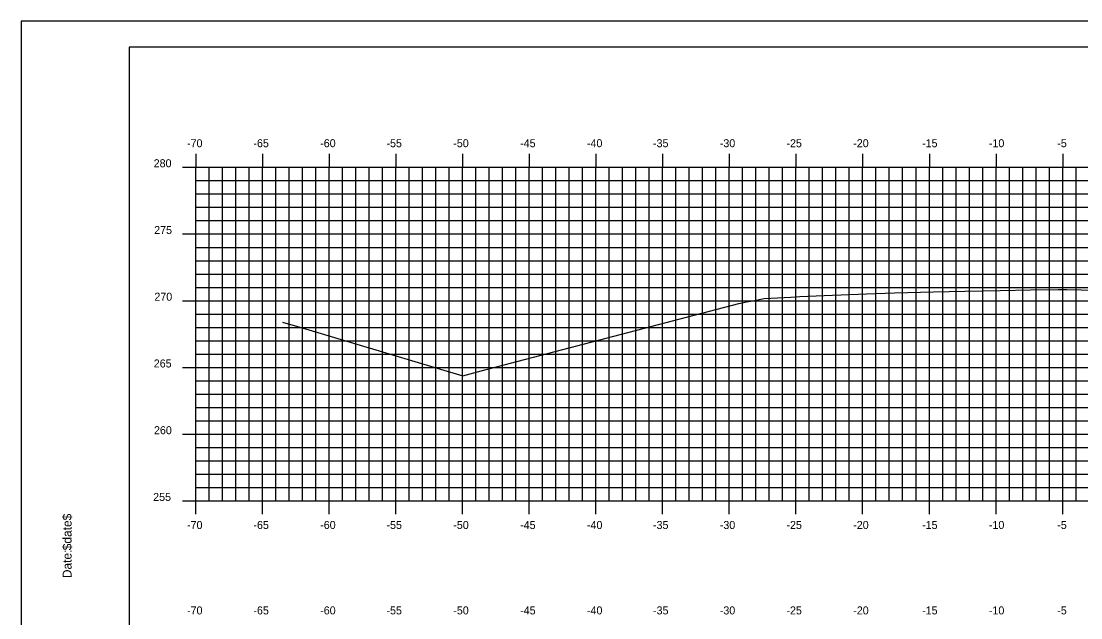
# Model space of a CAD drawing. Extents: x 1168600 to 1177589, y 610178 to 611246.
# Drawn here: x 1176530.8 to 1176610.3, y 610334 to 610378.7 of the extents above; entities that cross this region are included whole.
import ezdxf

# ---------------------------------------------------------------- set-up
doc = ezdxf.new("R2010")
doc.units = 0
for name, color, linetype in [('_Construction', 7, 'Continuous'), ('_Station Equation', 7, 'Continuous'), ('H_V ANNOTATION', 7, 'Continuous'), ('MAJOR', 7, 'Continuous'), ('MINOR', 7, 'Continuous')]:
    doc.layers.add(name, color=color, linetype=linetype)

msp = doc.modelspace()

# ---------------------------------------------------------------- linework, layer by layer
at = {"layer": '_Construction'}
for p, q in [((1176698.898, 610376.801), (1176538.898, 610376.801)), ((1176538.898, 610376.801), (1176538.898, 610271.801))]:
    msp.add_line(p, q, dxfattribs=at)
msp.add_lwpolyline([(1176530.805, 610268.742), (1176700.805, 610268.742), (1176700.805, 610378.742), (1176530.805, 610378.742)], close=True, dxfattribs=at)
at = {"layer": '_Station Equation'}
msp.add_lwpolyline([(1176550.398, 610356.197), (1176551.869, 610355.767), (1176563.916, 610352.178), (1176565.302, 610352.546), (1176584.623, 610357.603), (1176585.198, 610357.717), (1176585.676, 610357.795), (1176586.504, 610357.963), (1176588.524, 610358.079), (1176589.187, 610358.112), (1176591.022, 610358.191), (1176594.194, 610358.328), (1176596.297, 610358.382), (1176599.2, 610358.457), (1176601.571, 610358.508), (1176604.206, 610358.563), (1176606.485, 610358.607), (1176608.566, 610358.646), (1176608.924, 610358.641), (1176609.213, 610358.637), (1176611.353, 610358.595)], dxfattribs=at)
at = {"layer": 'MAJOR'}
for p, q in [((1176543.898, 610368.803), (1176543.898, 610367.801)), ((1176548.898, 610368.803), (1176548.898, 610367.801)), ((1176553.898, 610368.803), (1176553.898, 610367.801)), ((1176558.898, 610368.803), (1176558.898, 610367.801)), ((1176563.898, 610368.803), (1176563.898, 610367.801)), ((1176568.898, 610368.803), (1176568.898, 610367.801)), ((1176573.898, 610368.803), (1176573.898, 610367.801)), ((1176578.898, 610368.803), (1176578.898, 610367.801)), ((1176583.898, 610368.803), (1176583.898, 610367.801)), ((1176588.898, 610368.803), (1176588.898, 610367.801)), ((1176593.898, 610368.803), (1176593.898, 610367.801)), ((1176598.898, 610368.803), (1176598.898, 610367.801)), ((1176603.898, 610368.803), (1176603.898, 610367.801)), ((1176608.898, 610368.803), (1176608.898, 610367.801)), ((1176542.896, 610367.801), (1176543.898, 610367.801)), ((1176543.898, 610367.801), (1176683.898, 610367.801)), ((1176543.898, 610342.801), (1176543.898, 610367.801)), ((1176543.898, 610342.801), (1176543.898, 610367.801)), ((1176543.898, 610367.801), (1176683.898, 610367.801)), ((1176548.898, 610342.801), (1176548.898, 610367.801)), ((1176553.898, 610342.801), (1176553.898, 610367.801)), ((1176558.898, 610342.801), (1176558.898, 610367.801)), ((1176563.898, 610342.801), (1176563.898, 610367.801)), ((1176568.898, 610342.801), (1176568.898, 610367.801)), ((1176573.898, 610342.801), (1176573.898, 610367.801)), ((1176578.898, 610342.801), (1176578.898, 610367.801)), ((1176583.898, 610342.801), (1176583.898, 610367.801)), ((1176588.898, 610342.801), (1176588.898, 610367.801)), ((1176593.898, 610342.801), (1176593.898, 610367.801)), ((1176598.898, 610342.801), (1176598.898, 610367.801)), ((1176603.898, 610342.801), (1176603.898, 610367.801)), ((1176608.898, 610342.801), (1176608.898, 610367.801)), ((1176542.896, 610362.801), (1176543.898, 610362.801)), ((1176543.898, 610362.801), (1176683.898, 610362.801)), ((1176542.896, 610357.801), (1176543.898, 610357.801)), ((1176543.898, 610357.801), (1176683.898, 610357.801)), ((1176542.896, 610352.801), (1176543.898, 610352.801)), ((1176543.898, 610352.801), (1176683.898, 610352.801)), ((1176542.896, 610347.801), (1176543.898, 610347.801)), ((1176543.898, 610347.801), (1176683.898, 610347.801)), ((1176542.896, 610342.801), (1176543.898, 610342.801)), ((1176543.898, 610342.801), (1176683.898, 610342.801)), ((1176543.898, 610342.801), (1176683.898, 610342.801)), ((1176543.898, 610341.799), (1176543.898, 610342.801)), ((1176548.898, 610341.799), (1176548.898, 610342.801)), ((1176553.898, 610341.799), (1176553.898, 610342.801)), ((1176558.898, 610341.799), (1176558.898, 610342.801)), ((1176563.898, 610341.799), (1176563.898, 610342.801)), ((1176568.898, 610341.799), (1176568.898, 610342.801)), ((1176573.898, 610341.799), (1176573.898, 610342.801)), ((1176578.898, 610341.799), (1176578.898, 610342.801)), ((1176583.898, 610341.799), (1176583.898, 610342.801)), ((1176588.898, 610341.799), (1176588.898, 610342.801)), ((1176593.898, 610341.799), (1176593.898, 610342.801)), ((1176598.898, 610341.799), (1176598.898, 610342.801)), ((1176603.898, 610341.799), (1176603.898, 610342.801)), ((1176608.898, 610341.799), (1176608.898, 610342.801))]:
    msp.add_line(p, q, dxfattribs=at)
at = {"layer": 'MINOR'}
for p, q in [((1176544.898, 610342.801), (1176544.898, 610367.801)), ((1176545.898, 610342.801), (1176545.898, 610367.801)), ((1176546.898, 610342.801), (1176546.898, 610367.801)), ((1176547.898, 610342.801), (1176547.898, 610367.801)), ((1176549.898, 610342.801), (1176549.898, 610367.801)), ((1176550.898, 610342.801), (1176550.898, 610367.801)), ((1176551.898, 610342.801), (1176551.898, 610367.801)), ((1176552.898, 610342.801), (1176552.898, 610367.801)), ((1176554.898, 610342.801), (1176554.898, 610367.801)), ((1176555.898, 610342.801), (1176555.898, 610367.801)), ((1176556.898, 610342.801), (1176556.898, 610367.801)), ((1176557.898, 610342.801), (1176557.898, 610367.801)), ((1176559.898, 610342.801), (1176559.898, 610367.801)), ((1176560.898, 610342.801), (1176560.898, 610367.801)), ((1176561.898, 610342.801), (1176561.898, 610367.801)), ((1176562.898, 610342.801), (1176562.898, 610367.801)), ((1176564.898, 610342.801), (1176564.898, 610367.801)), ((1176565.898, 610342.801), (1176565.898, 610367.801)), ((1176566.898, 610342.801), (1176566.898, 610367.801)), ((1176567.898, 610342.801), (1176567.898, 610367.801)), ((1176569.898, 610342.801), (1176569.898, 610367.801)), ((1176570.898, 610342.801), (1176570.898, 610367.801)), ((1176571.898, 610342.801), (1176571.898, 610367.801)), ((1176572.898, 610342.801), (1176572.898, 610367.801)), ((1176574.898, 610342.801), (1176574.898, 610367.801)), ((1176575.898, 610342.801), (1176575.898, 610367.801)), ((1176576.898, 610342.801), (1176576.898, 610367.801)), ((1176577.898, 610342.801), (1176577.898, 610367.801)), ((1176579.898, 610342.801), (1176579.898, 610367.801)), ((1176580.898, 610342.801), (1176580.898, 610367.801)), ((1176581.898, 610342.801), (1176581.898, 610367.801)), ((1176582.898, 610342.801), (1176582.898, 610367.801)), ((1176584.898, 610342.801), (1176584.898, 610367.801)), ((1176585.898, 610342.801), (1176585.898, 610367.801)), ((1176586.898, 610342.801), (1176586.898, 610367.801)), ((1176587.898, 610342.801), (1176587.898, 610367.801)), ((1176589.898, 610342.801), (1176589.898, 610367.801)), ((1176590.898, 610342.801), (1176590.898, 610367.801)), ((1176591.898, 610342.801), (1176591.898, 610367.801)), ((1176592.898, 610342.801), (1176592.898, 610367.801)), ((1176594.898, 610342.801), (1176594.898, 610367.801)), ((1176595.898, 610342.801), (1176595.898, 610367.801)), ((1176596.898, 610342.801), (1176596.898, 610367.801)), ((1176597.898, 610342.801), (1176597.898, 610367.801)), ((1176599.898, 610342.801), (1176599.898, 610367.801)), ((1176600.898, 610342.801), (1176600.898, 610367.801)), ((1176601.898, 610342.801), (1176601.898, 610367.801)), ((1176602.898, 610342.801), (1176602.898, 610367.801)), ((1176604.898, 610342.801), (1176604.898, 610367.801)), ((1176605.898, 610342.801), (1176605.898, 610367.801)), ((1176606.898, 610342.801), (1176606.898, 610367.801)), ((1176607.898, 610342.801), (1176607.898, 610367.801)), ((1176609.898, 610342.801), (1176609.898, 610367.801)), ((1176543.898, 610366.801), (1176683.898, 610366.801)), ((1176543.898, 610366.801), (1176544.9, 610366.801)), ((1176543.898, 610365.801), (1176683.898, 610365.801)), ((1176543.898, 610365.801), (1176544.9, 610365.801)), ((1176543.898, 610364.801), (1176683.898, 610364.801)), ((1176543.898, 610364.801), (1176544.9, 610364.801)), ((1176543.898, 610363.801), (1176683.898, 610363.801)), ((1176543.898, 610363.801), (1176544.9, 610363.801)), ((1176543.898, 610361.801), (1176683.898, 610361.801)), ((1176543.898, 610361.801), (1176544.9, 610361.801)), ((1176543.898, 610360.801), (1176683.898, 610360.801)), ((1176543.898, 610360.801), (1176544.9, 610360.801)), ((1176543.898, 610359.801), (1176683.898, 610359.801)), ((1176543.898, 610359.801), (1176544.9, 610359.801)), ((1176543.898, 610358.801), (1176683.898, 610358.801)), ((1176543.898, 610358.801), (1176544.9, 610358.801)), ((1176543.898, 610356.801), (1176683.898, 610356.801)), ((1176543.898, 610356.801), (1176544.9, 610356.801)), ((1176543.898, 610355.801), (1176683.898, 610355.801)), ((1176543.898, 610355.801), (1176544.9, 610355.801)), ((1176543.898, 610354.801), (1176683.898, 610354.801)), ((1176543.898, 610354.801), (1176544.9, 610354.801)), ((1176543.898, 610353.801), (1176683.898, 610353.801)), ((1176543.898, 610353.801), (1176544.9, 610353.801)), ((1176543.898, 610351.801), (1176683.898, 610351.801)), ((1176543.898, 610351.801), (1176544.9, 610351.801)), ((1176543.898, 610350.801), (1176683.898, 610350.801)), ((1176543.898, 610350.801), (1176544.9, 610350.801)), ((1176543.898, 610349.801), (1176683.898, 610349.801)), ((1176543.898, 610349.801), (1176544.9, 610349.801)), ((1176543.898, 610348.801), (1176683.898, 610348.801)), ((1176543.898, 610348.801), (1176544.9, 610348.801)), ((1176543.898, 610346.801), (1176683.898, 610346.801)), ((1176543.898, 610346.801), (1176544.9, 610346.801)), ((1176543.898, 610345.801), (1176683.898, 610345.801)), ((1176543.898, 610345.801), (1176544.9, 610345.801)), ((1176543.898, 610344.801), (1176683.898, 610344.801)), ((1176543.898, 610344.801), (1176544.9, 610344.801)), ((1176543.898, 610343.801), (1176683.898, 610343.801)), ((1176543.898, 610343.801), (1176544.9, 610343.801))]:
    msp.add_line(p, q, dxfattribs=at)

# ---------------------------------------------------------------- texts
at = {"layer": '_Construction'}
for s, p in [('$date$', (1176534.583, 610339.106)), ('Date:', (1176534.583, 610337.018))]:
    msp.add_text(s, height=0.6696, rotation=90, dxfattribs=at).set_placement(p)
at = {"layer": 'H_V ANNOTATION'}
for s, p in [('-70', (1176543.24, 610369.301)), ('-65', (1176548.216, 610369.301)), ('-60', (1176553.224, 610369.301)), ('-55', (1176558.194, 610369.301)), ('-50', (1176563.202, 610369.301)), ('-45', (1176568.216, 610369.301)), ('-40', (1176573.224, 610369.301)), ('-35', (1176578.178, 610369.301)), ('-30', (1176583.186, 610369.301)), ('-25', (1176588.183, 610369.301)), ('-20', (1176593.191, 610369.301)), ('-15', (1176598.355, 610369.301)), ('-10', (1176603.363, 610369.301)), ('-5', (1176608.489, 610369.301)), ('280', (1176540.739, 610367.801)), ('275', (1176540.776, 610362.801)), ('270', (1176540.792, 610357.801)), ('265', (1176540.744, 610352.801)), ('260', (1176540.76, 610347.801)), ('255', (1176540.701, 610342.801)), ('-70', (1176543.24, 610340.701)), ('-65', (1176548.216, 610340.701)), ('-60', (1176553.224, 610340.701)), ('-55', (1176558.194, 610340.701)), ('-50', (1176563.202, 610340.701)), ('-45', (1176568.216, 610340.701)), ('-40', (1176573.224, 610340.701)), ('-35', (1176578.178, 610340.701)), ('-30', (1176583.186, 610340.701)), ('-25', (1176588.183, 610340.701)), ('-20', (1176593.191, 610340.701)), ('-15', (1176598.355, 610340.701)), ('-10', (1176603.363, 610340.701)), ('-5', (1176608.489, 610340.701)), ('-70', (1176543.24, 610334.301)), ('-65', (1176548.216, 610334.301)), ('-60', (1176553.224, 610334.301)), ('-55', (1176558.194, 610334.301)), ('-50', (1176563.202, 610334.301)), ('-45', (1176568.216, 610334.301)), ('-40', (1176573.224, 610334.301)), ('-35', (1176578.178, 610334.301)), ('-30', (1176583.186, 610334.301)), ('-25', (1176588.183, 610334.301)), ('-20', (1176593.191, 610334.301)), ('-15', (1176598.355, 610334.301)), ('-10', (1176603.363, 610334.301)), ('-5', (1176608.489, 610334.301))]:
    msp.add_text(s, height=0.6, dxfattribs=at).set_placement(p)

doc.saveas('drawing.dxf')
